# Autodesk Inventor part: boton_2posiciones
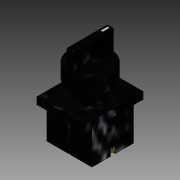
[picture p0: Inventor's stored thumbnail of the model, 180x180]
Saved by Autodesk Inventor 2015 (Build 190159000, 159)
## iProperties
Created: 2016-04
Part Number: boton_2posiciones
Material: Genérico
Document SubType Name: Modeling
Designer: Diego
Density: 1 g/cm^3
Appearance: Valor por defecto
Author: Diego
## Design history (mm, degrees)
sketch "Boceto1"
  geometry: C1 r 15 at (0, 0); 1 further point
  constraints: 1 centre point, 1 coincident
  dimensions: "d0" = 30 diameter of C1
extrude "Extrusión1" new body sketch "Boceto1" distance "d1" = 10; taper "d2" = 0 deg
sketch "Boceto2"
  geometry: L1 (-2.499, -14.79)-(-2.504, 14.79); L2 (-2.504, 14.79)-(2.501, 14.79); L3 (2.496, 14.79)-(2.501, -14.79); L4 (2.501, -14.79)-(2.501, 14.79); A1 r 15 centre (0, 0) between (-2.504, 14.79) and (-2.499, -14.79) reference; A2 r 15 centre (0, 0) between (-2.499, -14.79) and (2.501, -14.79); A3 r 14.955 centre (-0.002, 0.046) between (2.501, 14.79) and (-2.504, 14.79); 2 further points
  constraints: 8 end point, 7 point on circle, 2 centre point, 1 coincident, 1 horizontal, 1 vertical, 3 other
  dimensions: "d4" = 5 distance of L3.end L1.start; "d5" = 5 distance of L1.end L3.start
extrude "Extrusión2" join sketch "Boceto2" distance "d7" = 15; taper "d8" = 0 deg
fillet "Empalme1" dims "d9" = 1
fillet "Empalme2" dims "d10" = 1
sketch "Boceto3"
  geometry: L1 (0, 13.192)-(-0.8, 13.192); L2 (-0.8, 13.192)-(0.8, 13.192); L3 (0.8, 13.192)-(0.8, 8.192); L4 (0.8, 8.192)-(-0.8, 8.192); L5 (-0.8, 8.192)-(-0.8, 13.192); 1 further point
  constraints: 10 end point, 2 perpendicular, 1 horizontal, 1 point on line
  dimensions: "d11" = 0.8 distance of L1.start L1.end; "d12" = 1.6 distance of L1.end L2.end; "d13" = 5 distance of L2.end L3.end; "d14" = 1.6 distance of L3.end L4.end
extrude "Extrusión3" cut sketch "Boceto3" distance "d15" = 0.5; taper "d16" = 0 deg
sketch "Boceto4"
  geometry: C1 r 10 at (0, 0); 1 further point
  constraints: 1 centre point, 1 coincident
  dimensions: "d17" = 20 diameter of C1
extrude "Extrusión4" join sketch "Boceto4" distance "d18" = 10; taper "d19" = 0 deg
sketch "Boceto5"
  geometry: L1 (-17.484, 20.693)-(17.564, 20.693); L2 (17.564, 20.693)-(17.564, -20.853); L3 (17.564, -20.853)-(-17.484, -20.853); L4 (-17.484, -20.853)-(-17.484, 20.693); A1 r 15 centre (0, 0) between (-1.456, 14.929) and (-1.608, -14.914) reference; 1 further point
  constraints: 8 end point, 2 parallel, 1 horizontal, 1 perpendicular
extrude "Extrusión5" join sketch "Boceto5" distance "d20" = 5; taper "d21" = 0 deg
sketch "Boceto9"
  geometry: L1 (0.39, -14.914)-(16.39, -14.914); L2 (16.39, -14.914)-(16.39, 14.911); L3 (16.39, 14.911)-(0.39, 14.911); L4 (0.39, 14.911)-(0.39, -14.914); L5 (-0.203, -14.914)-(-16.203, -14.914); L6 (-16.203, -14.914)-(-16.203, 14.911); L7 (-16.203, 14.911)-(-0.203, 14.911); L8 (-0.203, 14.911)-(-0.203, -14.914); 1 further point
  constraints: 16 end point, 4 parallel, 2 horizontal, 2 perpendicular, 2 point on line
  dimensions: "d26" = 16 distance of L3.end L2.end; "d27" = 16 distance of L6.end L7.end
extrude "Extrusión7" join sketch "Boceto9" distance "d28" = 25; taper "d29" = 0 deg
sketch "Boceto10"
  geometry: L1 (-16.203, 14.911)-(-0.203, 14.911) reference; L2 (-8.203, 14.911)-(-8.203, -14.914); L3 (-16.203, -14.914)-(-0.203, -14.914) reference; L4 (16.39, 14.911)-(0.39, 14.911) reference; L5 (8.39, 14.911)-(8.39, -14.914); L6 (16.39, -14.914)-(0.39, -14.914) reference; L7 (-16.203, -14.914)-(-16.203, 14.911) reference; L8 (16.39, 14.911)-(16.39, -14.914) reference; L9 (-16.203, 7.715)-(16.39, 7.715); L10 (-16.203, -8.047)-(16.39, -8.047); A1 r 15 centre (0, 0) between (1.607, -14.914) and (1.635, 14.911) reference; 8 further points
  constraints: 12 point on line, 8 end point, 4 midpoint, 2 perpendicular, 1 horizontal alignment, 1 point on circle, 1 other
hole "Agujero1" sketch "Boceto10" at (-15, 0), (15, 0), (-8.203, -8.047), (8.39, -8.047), (-8.203, 7.715), (8.39, 7.715) diameter "d30" = 4; stored, may be unused: countersink angle "d34" = 90 deg, drill point angle "d36" = 0 deg; dims "d31" = 6, "d32" = 4, "d33" = 2, "d35" = 5
sketch "Boceto11"
  geometry: C1 r 1.75 at (0, 0); C2 r 2 at (6.797, 7.715) reference; C3 r 1.75 at (6.797, 7.715); C4 r 2 at (23.39, 7.715) reference; C5 r 1.75 at (23.39, 7.715); C6 r 2 at (6.797, -8.047) reference; C7 r 1.75 at (6.797, -8.047); C8 r 2 at (23.39, -8.047) reference; C9 r 1.75 at (23.39, -8.047); C10 r 1.75 at (30, 0); A1 r 2 centre (0, 0) between (-1.203, -1.598) and (-1.203, 1.598) reference; A2 r 15 centre (15, 0) between (16.607, -14.914) and (16.635, 14.911) reference; 1 further point
  constraints: 6 centre point, 5 coincident, 1 point on circle
  dimensions: "d37" = 3.5 diameter of C1; "d38" = 3.5 diameter of C3; "d39" = 3.5 diameter of C5; "d40" = 3.5 diameter of C7; "d41" = 3.5 diameter of C9; "d42" = 3.5 diameter of C10
extrude "Extrusión8" join sketch "Boceto11" distance "d43" = 3; taper "d44" = 0 deg
node "Sólido1"
